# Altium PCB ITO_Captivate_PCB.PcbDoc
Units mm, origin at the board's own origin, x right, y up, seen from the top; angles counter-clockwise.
Board outline 77 x 64 mm, 2 copper layers (Top Layer, Bottom Layer), stack 1.575 mm thick; 24 components, 38 nets, 142 pads, 26 vias.
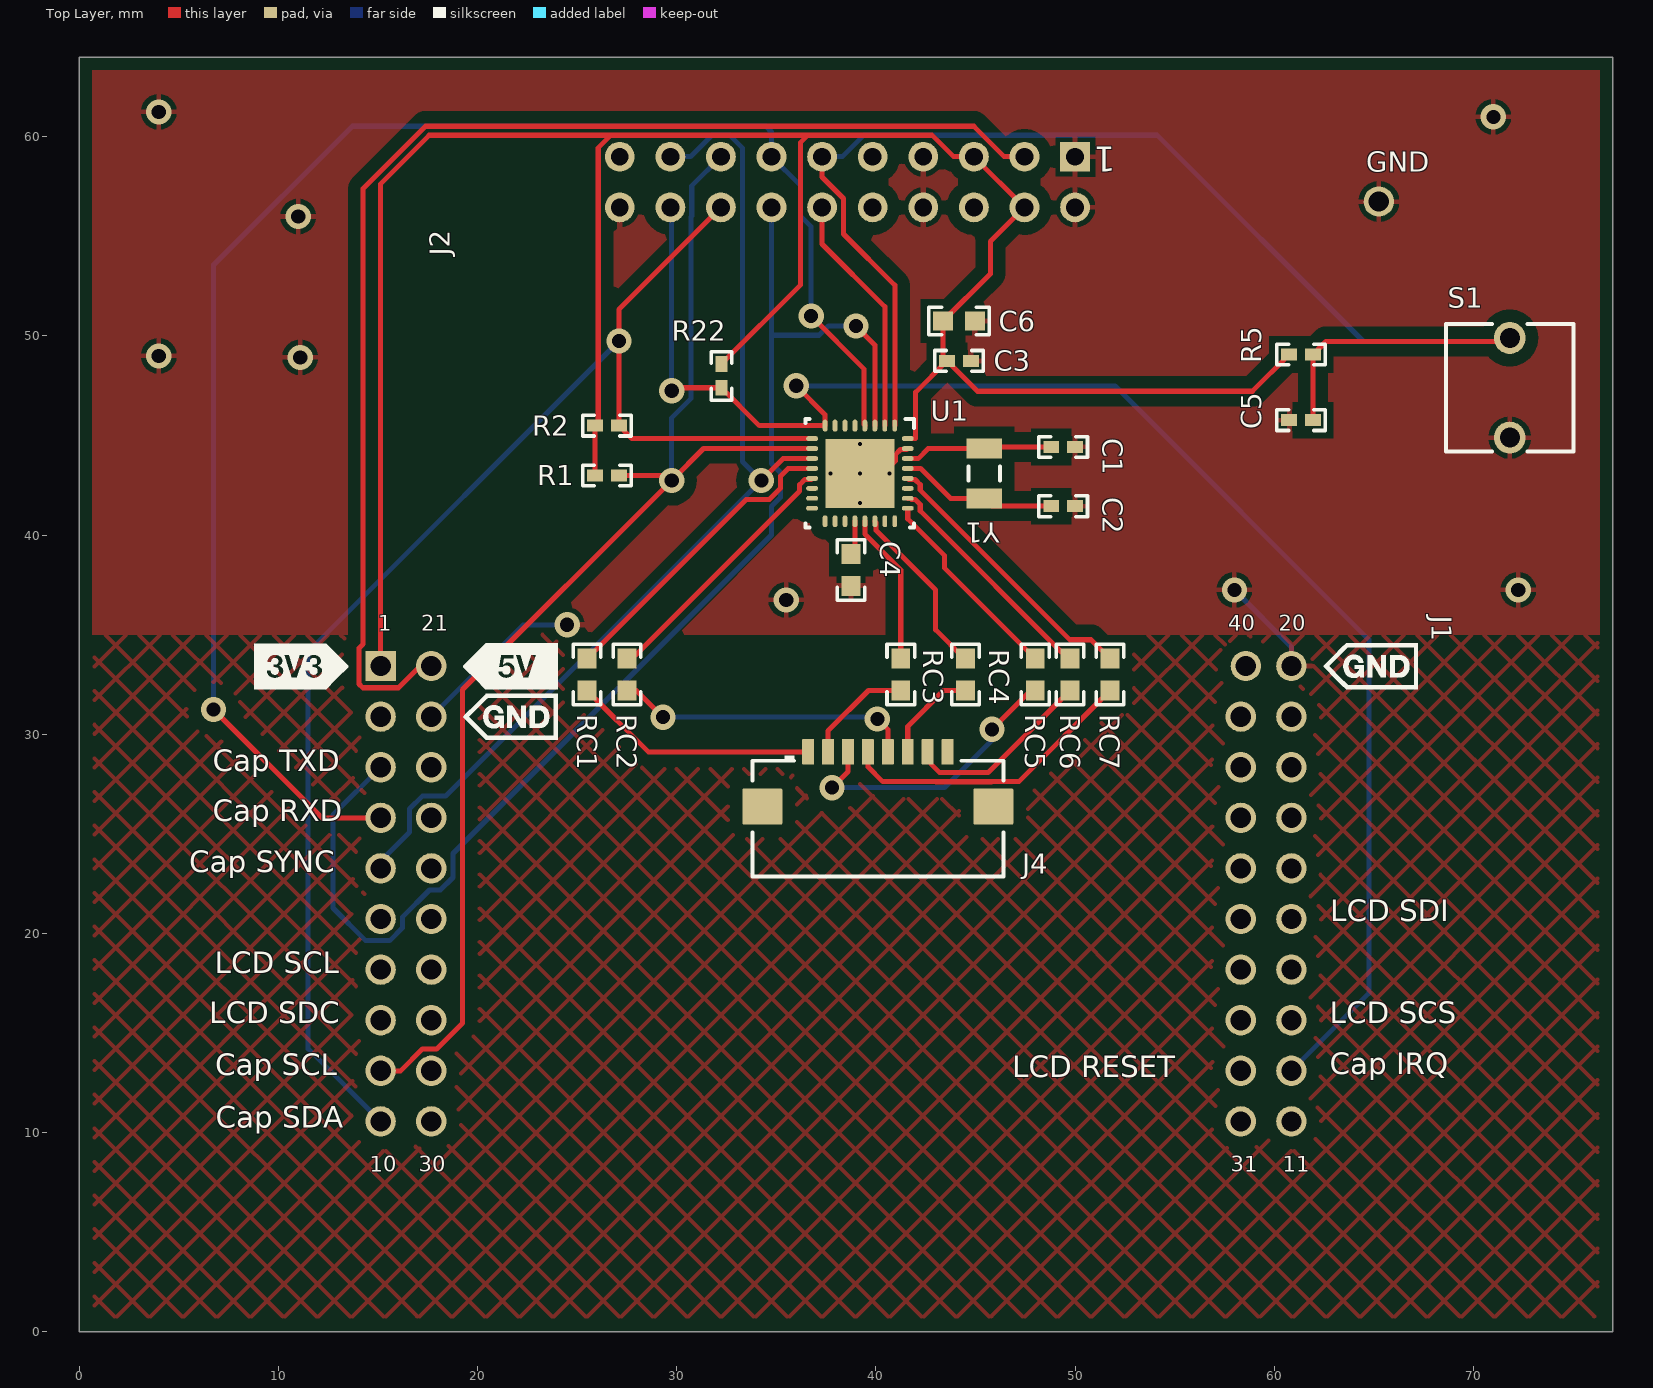
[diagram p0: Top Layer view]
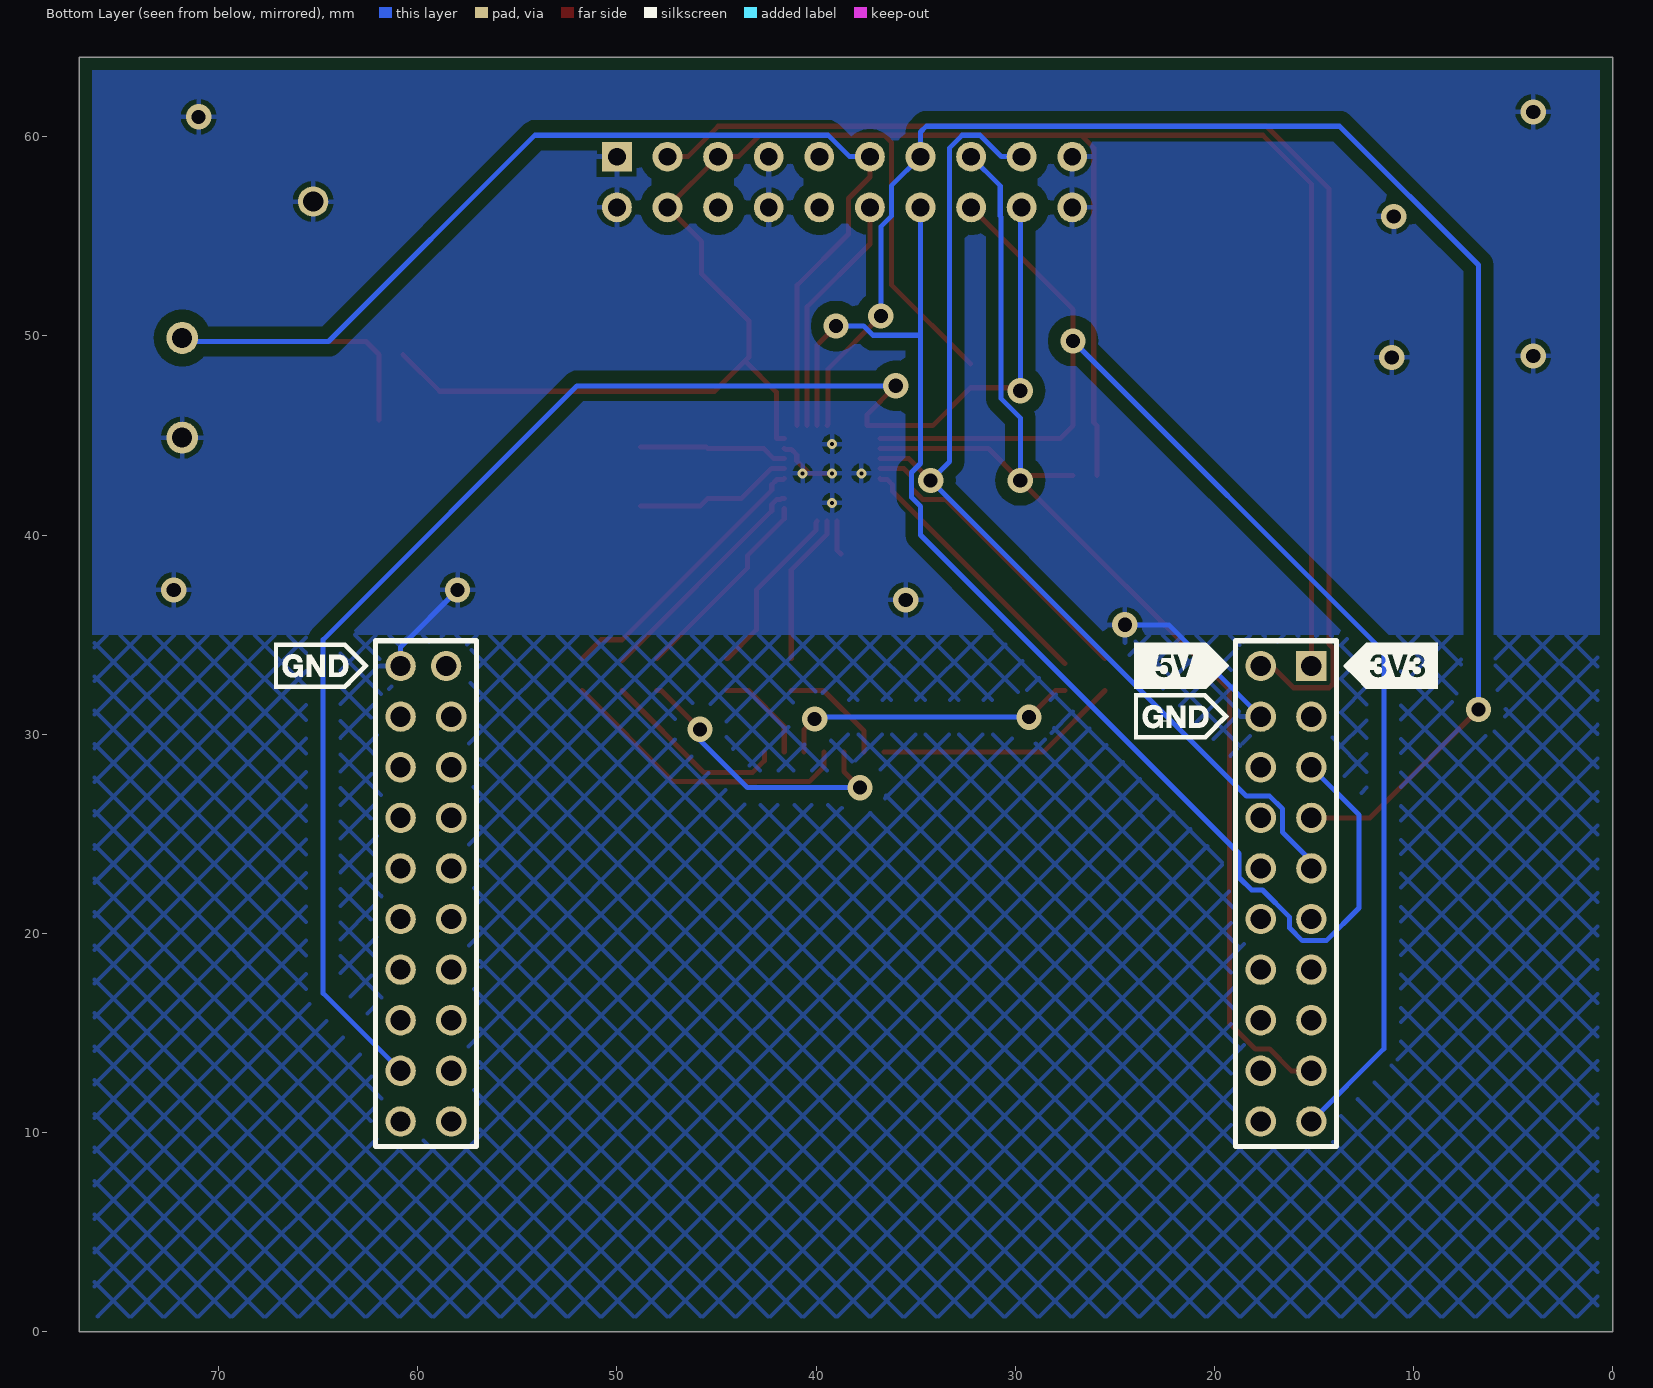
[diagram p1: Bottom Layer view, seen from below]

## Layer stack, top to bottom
Top Solder: solder mask 0.0102, Solder Resist, Dk 3.5
Top Layer: signal copper 0.0356
Dielectric1: core 1.5037, FR-4, Dk 4.8
Bottom Layer: signal copper 0.0356
Bottom Solder: solder mask 0.0102, Solder Resist, Dk 3.5

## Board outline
0,0 77,0 77,64 0,64

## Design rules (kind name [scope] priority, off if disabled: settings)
AcuteAngle [All] p1: minimum=4.50000000000000E+0001 checktracksonly=FALSE
AssemblyTestPointUsage [All] p1: valid=2
BoardOutlineClearance BoardOutlineClearance_MountingHoles [OnCopper and InComponentClass('Mounting Holes')] p1: gap=1.016
BoardOutlineClearance BoardOutlineClearance_Poly [OnCopper and IsPoly] p2: gap=0.635
BoardOutlineClearance [OnCopper and Not InComponentClass('Logo') and not InComponentClass('FiducialMark') and not InRegion(1000,500,4000,800) and not InPoly] p3: gap=1.905
Clearance Clearance_Keepouts [((IsTrack Or IsArc) And Not InPoly) And IsFree and IsKeepOut vs ((IsTrack Or IsArc) And Not InPoly) And IsFree and IsKeepOut] p1: gap=0
Clearance Clearance_Poly [InPolygon] p2: gap=0.635
Clearance [All] p3: gap=0.2
ComponentClearance ComponentClearance_MountingHoles_FiducialMarks [InComponentClass('Mounting Holes') vs InComponentClass('FiducialMark')] p1: gap=1.27 collisioncheckmode=3 verticalgap=0.254 showdistances=FALSE
ComponentClearance ComponentClearance_Shunt [InComponentClass('Header') vs InComponentClass('Shunt')] p2: gap=0 collisioncheckmode=3 verticalgap=0 showdistances=FALSE
ComponentClearance ComponentClearance_Logo [InComponentClass('Logo')] p3: gap=1.27 collisioncheckmode=3 verticalgap=0.254 showdistances=FALSE
ComponentClearance ComponentClearance_ScrewToNut [(HasFootprint('NY PMS 440 0025 PH')) vs (HasFootprint('Keystone_1902C'))] p4: gap=0.127 collisioncheckmode=3 verticalgap=0.254 showdistances=FALSE
ComponentClearance ComponentClearance_MountingHoles [InComponentClass('Mounting Holes')] p5: gap=6.35 collisioncheckmode=3 verticalgap=2540 showdistances=FALSE
ComponentClearance ComponentClearance_SmallPassives [HasFootprint('0201*') or HasFootprint('0402*') or HasFootprint('0508') or HasFootprint('0603*') or HasFootprint('0612') or HasFootprint('0805*') or HasFootprint('0815*') or HasFootprint('0830*') or HasFootprint('1206*') or HasFootprint('1210*') or HasFootprint('1808*') or HasFootprint('1812*') or HasFootprint('1825*') or HasFootprint('2010*') or HasFootprint('2220*') or HasFootprint('2225*') or HasFootprint('2512*') or HasFootprint('2728*') or HasFootprint('3518*') vs HasFootprint('0201*') or HasFootprint('0402*') or HasFootprint('0508') or HasFootprint('0603*') or HasFootprint('0612') or HasFootprint('0805*') or HasFootprint('0815*') or HasFootprint('0830*') or HasFootprint('1206*') or HasFootprint('1210*') or HasFootprint('1808*') or HasFootprint('1812*') or HasFootprint('1825*') or HasFootprint('2010*') or HasFootprint('2220*') or HasFootprint('2225*') or HasFootprint('2512*') or HasFootprint('2728*') or HasFootprint('3518*')] p6: gap=0.38 collisioncheckmode=3 verticalgap=0.254 showdistances=FALSE
ComponentClearance ComponentClearance_THtoSMT [IsThruComponent vs IsSMTComponent] p7: gap=1.016 collisioncheckmode=3 verticalgap=0.762 showdistances=FALSE
ComponentClearance ComponentClearance_THtoTH [IsThruComponent vs IsThruComponent] p8: gap=0.762 collisioncheckmode=3 verticalgap=0.762 showdistances=FALSE
ComponentClearance [All] p9: gap=0.762 collisioncheckmode=3 verticalgap=0.254 showdistances=FALSE
DiffPairsRouting [All] p1: maxlimit=2.54 minlimit=0.254 mostfreqgap=0.254 toplayer_minwidth=0.381 toplayer_maxwidth=0.381 toplayer_prefwidth=0.381 bottomlayer_minwidth=0.381 bottomlayer_maxwidth=0.381 bottomlayer_prefwidth=0.381 maxuncoupledlength=25.4
FabricationTestPointUsage TestPointUsage [All] p1: valid=2 allowmultiple=FALSE
FabricationTestpoint Testpoint [All] p1: side=3 testpointundercomponent=TRUE minsize=1.016 maxsize=2.54 preferedsize=1.524 minholesize=0 maxholesize=1.016 preferedholesize=0.813 testpointgrid=0.025 allowsidetop=TRUE allowsidebottom=TRUE usegrid=TRUE gridtolerance=0
FanoutControl Fanout_LCC [IsLCC] p1: bgadir=Out bgaviamode=Centered fanoutstyle=Auto fanoutdirection=Alternating viagrid=0.025 // Fanout_LCC (Default Rule)
FanoutControl Fanout_BGA [IsBGA] p2: bgadir=Out bgaviamode=Centered fanoutstyle=Auto fanoutdirection=Alternating viagrid=0.025 // Fanout_BGA (Default Rule)
FanoutControl Fanout_Default [All] p4: bgadir=Out bgaviamode=Centered fanoutstyle=Auto fanoutdirection=Alternating viagrid=0.025 // Fanout_Default (Default Rule)
FanoutControl Fanout_Small [(CompPinCount < 5)] p5: bgadir=Out bgaviamode=Centered fanoutstyle=Auto fanoutdirection=OutThenIn viagrid=0.025 // Fanout_Small (Default Rule)
HoleSize [All] p1: absolutevalues=TRUE maxlimit=6.375 minlimit=0.2 maxpercent=80.000 minpercent=20.000
MinimumAnnularRing MinimumAnnularRing_ThermalPadVias [IsVia and InAnyComponent] p1: minimumring=0.15
MinimumAnnularRing [All] p2: minimumring=0.203
MinimumSolderMaskSliver MinimumSolderMaskSliver_Logo [InComponentClass('Logo') vs InComponentClass('Logo')] p1: minsoldermaskwidth=0.018
MinimumSolderMaskSliver [All] p2: minsoldermaskwidth=0.1
PlaneConnect [All] p1: planeconnectstyle=Relief reliefexpansion=0.254 reliefentries=4 reliefconductorwidth=0.254 reliefairgap=0.254
PolygonConnect [All] p1: connectstyle=Relief reliefconductorwidth=0.254 reliefentries=4 polygonreliefangle="90 Angle" airgapwidth=0.254
RoutingVias ThermalPadVias [IsVia and InAnyComponent] p1: holewidth=0.2 width=0.5 viastyle="Through Hole" minholewidth=0.2 minwidth=0.5 maxholewidth=0.33 maxwidth=0.6
RoutingVias [All] p2: holewidth=0.406 width=0.864 viastyle="Through Hole" minholewidth=0.2 minwidth=0.66 maxholewidth=1.016 maxwidth=1.651
SilkToBoardRegionClearance [Not ((IsComment or IsDesignator) And (Hide <> 'False')) and not InRegion(1000,500,4000,800)] p1:
SilkToSilkClearance SilkToSilkClearance_Pb-FreeLogo [(HasFootprint('Pb-Free_Overlay_Medium') OR HasFootprint('Pb-Free_Overlay_Small')) vs (HasFootprint('Pb-Free_Overlay_Medium') OR HasFootprint('Pb-Free_Overlay_Small'))] p1: silktosilkclearance=0
SilkToSilkClearance [All] p2: silktosilkclearance=0.102
SilkToSolderMaskClearance SilkToComponentPadClearance [IsPad and InAnycomponent] p1: minsilkscreentomaskgap=0.127 clearancetoexposedcopper=TRUE
SilkToSolderMaskClearance "Silk to Solder Mask Opening" [All] p2: minsilkscreentomaskgap=0.102 clearancetoexposedcopper=FALSE
SolderMaskExpansion [All] p1: expansion=0.05
Width [All] p1: maxlimit=2.54 minlimit=0.152 preferedwidth=0.254 checkconnectedcopper=TRUE
15 further rules are at their usual default settings.

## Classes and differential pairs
component class Header: J1

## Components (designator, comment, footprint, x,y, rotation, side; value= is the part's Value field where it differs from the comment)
C1 "GRM1555C1H220JA01D" 0402 49.406,44.431 r0 top
C2 "GRM1555C1H220JA01D" 0402 49.406,41.456 r0 top
C3 "885012205037" 0402 44.175,48.75 r0 top
C4 "GRM188R61A105KA61D" 0603 38.75,38.25 r270 top
C5 "GRM155R61H102KA01D" 0402 61.35,45.775 r180 top
C6 "GRM185C81A475ME11D" 0603 44.175,50.75 r0 top
GND "TESTPOINT" TP_VIA_060RND040 65.25,56.75 r0 top
J1 "TSW-110-07-G-S" "40Pin BP" 38,22 r0 top
J2 "Connector 10X2RA" CONN2X10RA 50,59 r180 top
J4 "686108148922" Wurth_686108148922 40.1,27.75 r0 top
R1 "CRCW04022K20JNED" 0402 26.5,43 r180 top
R2 "CRCW04022K20JNED" 0402 26.5,45.5 r180 top
R5 "CRCW040247K0JNED" 0402 61.35,49.075 r180 top
R22 "CRCW040210K0JNED" 0402 32.25,48 r90 top
RC1 "ERJ-3GEY0R00V" 0603 25.5,33 r270 top
RC2 "ERJ-3GEY0R00V" 0603 27.5,33 r270 top
RC3 "ERJ-3GEY0R00V" 0603 41.25,33 r270 top
RC4 "ERJ-3GEY0R00V" 0603 44.5,33 r270 top
RC5 "ERJ-3GEY0R00V" 0603 48,33 r270 top
RC6 "ERJ-3GEY0R00V" 0603 49.75,33 r270 top
RC7 "ERJ-3GEY0R00V" 0603 51.75,33 r270 top
S1 "EVQ-21505R" SW_EVQ-21x05 71.825,47.4 r90 top
U1 "MSP430FR2633IRHB" RHB0032E 39.2,43.1 r270 top
Y1 "FC-135 32.7680KA-A3" Epson_FC-135 45.443,43.091 r270 top

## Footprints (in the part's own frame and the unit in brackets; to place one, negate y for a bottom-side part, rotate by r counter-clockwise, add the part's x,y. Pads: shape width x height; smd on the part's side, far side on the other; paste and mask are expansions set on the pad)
"40Pin BP" [mil] "40Pin Booster Pack Connection (Top - male; Bottom - female)"
  rect 60x60 hole 40: 1(-900,450)
  round 60 hole 40: 2(-900,350) 3(-900,250) 4(-900,150) 5(-900,50) 6(-900,-50) 7(-900,-150) 8(-900,-250) 9(-900,-350) 10(-900,-450) 11(900,-450) 12(900,-350) 13(900,-250) 14(900,-150) 15(900,-50) 16(900,50) 17(900,150) 18(900,250) 19(900,350) 20(900,450) 21(-800,450) 22(-800,350) 23(-800,250) 24(-800,150) 25(-800,50) 26(-800,-50) 27(-800,-150) 28(-800,-250) 29(-800,-350) 30(-800,-450) 31(800,-450) 32(800,-350) 33(800,-250) 34(800,-150) 35(800,-50) 36(800,50) 37(800,150) 38(800,250) 39(800,350) 40(810,450)
  silkscreen extent -1150,305 1150,495, body extent -950,-500 950,500, height 335
0402 [mm] "0402 from SM-752 data"
  rect 0.8x0.6 smd: 1(-0.6,0) 2(0.6,0)
  silkscreen extent -1.22,-0.52 1.22,0.52, body extent -0.55,-0.3 0.55,0.3, height 0.6
0603 [mm] "0603 from SM-752 data"
  rect 1x0.95 smd: 1(-0.8,0) 2(0.8,0)
  silkscreen extent -1.52,-0.69 1.52,0.69, body extent -0.87,-0.47 0.87,0.47, height 1
CONN2X10RA [mm] "Connector;F-Receptacle; 10x2 Position; Right Angle"
  rect 1.5x1.5 hole 0.9: 1(0,0)
  round 1.5 hole 0.9: 2(0,2.54) 3(2.54,0) 4(2.54,2.54) 5(5.08,0) 6(5.08,2.54) 7(7.62,0) 8(7.62,2.54) 9(10.16,0) 10(10.16,2.54) 11(12.7,0) 12(12.7,2.54) 13(15.24,0) 14(15.24,2.54) 15(17.78,0) 16(17.78,2.54) 17(20.32,0) 18(20.32,2.54) 19(22.86,0) 20(22.86,2.54)
  body extent -1.52,-10.03 24.38,-1.52, height 4.95
Epson_FC-135 [mm] "SMD, 2-Leads, Body 3.2x1.5mm"
  rect 1x1.8 smd: 1(-1.25,0) 2(1.25,0)
  silkscreen extent -0.35,-0.8 0.35,0.8, body extent -1.65,-0.8 1.65,0.8, height 0.9
RHB0032E [mm] "QFN, 32-Leads, Body 5x5mm, Pitch 0.5mm, Thermal Pad 3.45x3.45mm, TI Recommended"
  oval 0.6x0.24 smd: 1(-2.4,1.75) 2(-2.4,1.25) 3(-2.4,0.75) 4(-2.4,0.25) 5(-2.4,-0.25) 6(-2.4,-0.75) 7(-2.4,-1.25) 8(-2.4,-1.75) 17(2.4,-1.75) 18(2.4,-1.25) 19(2.4,-0.75) 20(2.4,-0.25) 21(2.4,0.25) 22(2.4,0.75) 23(2.4,1.25) 24(2.4,1.75)
  oval 0.24x0.6 smd: 9(-1.75,-2.4) 10(-1.25,-2.4) 11(-0.75,-2.4) 12(-0.25,-2.4) 13(0.25,-2.4) 14(0.75,-2.4) 15(1.25,-2.4) 16(1.75,-2.4) 25(1.75,2.4) 26(1.25,2.4) 27(0.75,2.4) 28(0.25,2.4) 29(-0.25,2.4) 30(-0.75,2.4) 31(-1.25,2.4) 32(-1.75,2.4)
  rect 3.45x3.45 smd paste-1.725: 33(0,0)
  silkscreen extent -2.72,-2.73 2.72,2.73, body extent -2.57,-2.57 2.58,2.58, height 1.01
SW_EVQ-21x05 [mm] "Panasonic"
  round 1.6 hole 1: 1(-2.5,0) 2(2.5,0)
  silkscreen extent -3.2,-3.2 3.2,3.2, body extent -3.15,-3.15 3.15,3.15, height 5.2
TP_VIA_060RND040 [mil] "TP_VIA_060RND040"
  round 60 hole 40: 1(0,0)
Wurth_686108148922 [mm] "FFC/FPC Connector, 8 POS, 1mm, R/A, SMT"
  rrect17% 0.6x1.3 smd: 1(-3.5,1.375) 2(-2.5,1.375) 3(-1.5,1.375) 4(-0.5,1.375) 5(0.5,1.375) 6(1.5,1.375) 7(2.5,1.375) 8(3.5,1.375)
  rrect6% 2x1.8 smd: MP1(-5.8,-1.375) MP2(5.8,-1.375)
  silkscreen extent -6.3,-4.87 6.3,1.2, body extent -6.3,-4.87 6.3,1.63, height 2.25

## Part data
C1 C2: "CAP, CERM, 22 pF, 50 V, +/- 5%, C0G/NP0, 0402"
C3: "CAP, CERM, 0.1 µF, 16 V, +/- 10%, X7R, 0402"
C4: "CAP, CERM, 1 µF, 10 V, +/- 10%, X5R, 0603"
C5: "CAP, CERM, 1000 pF, 50 V, +/- 10%, X5R, 0402"
C6: "CAP, CERM, 4.7 µF, 10 V, +/- 20%, X6S, 0603"
GND: "TEST POINT.  No entry in BOM."
J1: library part "BoosterPack Connector", "Header, 100mil, 10x1, Gold, TH"
J2: "Connector, Female, 10-Pin, 2 row, Right Angle"
J4: "FFC/FPC Connector, 8 POS, 1mm, Tin, R/A, SMT"
R1 R2: "RES, 2.2 k, 5%, 0.063 W, 0402"
R5: "RES, 47k ohm, 5%, 0.063W, 0402"
R22: "RES, 10 k, 5%, 0.063 W, 0402"
RC1 RC2 RC3 RC4 RC5 RC6 RC7: "RES, 0, 5%, 0.1 W, 0603"
S1: "Switch, Tactile, SPST-NO, 0.02A, 15V, TH"
U1: "MSP430 Captivate Microcontroller"
Y1: "Crystal, 32.768 KHz, 12.5 pF, SMD"

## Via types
v1: diameter 1.27, hole 0.711, Top Layer to Bottom Layer, 21 vias
v2: diameter 0.5, hole 0.2, Top Layer to Bottom Layer, 5 vias

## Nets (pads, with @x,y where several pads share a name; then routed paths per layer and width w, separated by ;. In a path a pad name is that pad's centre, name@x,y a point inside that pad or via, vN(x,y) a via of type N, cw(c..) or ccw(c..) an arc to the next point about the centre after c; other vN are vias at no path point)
BUTTON1: J4.1 RC1.2 | length 12.4
  Top Layer w0.254: RC1.2 28.575,29.125 J4.1
BUTTON2: J4.2 RC3.2 | length 5.5
  Top Layer w0.254: J4.2 37.6,30.175 39.625,32.2 RC3.2
BUTTON3: J4.3 RC5.2 | length 14.7
  Top Layer w0.254: v1(37.8,27.325) 38.6,28.125 J4.3 ; v1(45.825,30.25) 47.775,32.2 RC5.2
  Bottom Layer w0.254: v1(37.8,27.325) 43.45,27.325 45.825,29.7 v1(45.825,30.25)
EZFET_RXD: J2.9
EZFET_SBWTCK_TST: J2.12 U1.2 | length 12.3
  Top Layer w0.254: J2.12 37.3,54.62 40.45,51.47 U1.2
EZFET_SBWTDIO_RST: C5.1 J2.11 R5.1 S1.2 U1.1 | length 67.9
  Top Layer w0.254: J2.11 37.3,57.983 38.377,56.906 38.377,55.123 40.95,52.55 U1.1 ; C5.1 R5.1 62.6,49.725 71.65,49.725 S1.2
  Bottom Layer w0.254: J2.11 38.317,59 39.394,60.077 54.123,60.077 64.475,49.725 71.65,49.725 S1.2
EZFET_TXD: J2.10
GND: C1.2 C2.2 C3.2 C4.2 C5.2 C6.2 GND.1 J1.20 J1.22 J2.1 J2.2 J2.7 J2.8 J2.19 J2.20 S1.1 U1.31 U1.33 | length 16.8
  Top Layer w0.254: v2(39.2,43.1) 40.35,43.1 40.973,43.723 40.973,44.035 41.235,44.297 41.547,44.297 U1.31
  Bottom Layer w0.254: J1.22 22.29,35.5 v1(24.5,35.5) ; v1(58,37.25) 60.86,34.39 J1.20
  other v1: 35.5,36.75 72.25,37.25 11.1,48.925 4,49 11,56 71,61 4,61.25
  other v2: 39.2,41.625 37.725,43.1 40.675,43.1 39.2,44.575
LCD_SCL: J1.7
LCD_SCS: J1.13
LCD_SDC: J1.8
LCD_SDI: J1.15
MSP_IRQ: J1.12 J2.18 R22.1 U1.8 | length 77.9
  Top Layer w0.254: v1(29.75,47.25) 29.9,47.4 R22.1 34.15,45.5 U1.8 37.45,46.05 v1(36,47.5)
  Bottom Layer w0.254: J2.18 29.75,56.39 v1(29.75,47.25) ; v1(36,47.5) 36.25,47.75 36.5,47.5 52,47.5 64.75,34.75 64.75,17 J1.12
MSP_RXD: J1.4 J2.13 U1.4 | length 80.7
  Top Layer w0.254: v1(6.75,31.25) 12.19,25.81 J1.4 ; v1(36.75,51) 39.397,48.353 39.397,45.553 U1.4
  Bottom Layer w0.254: v1(6.75,31.25) 6.75,53.562 13.719,60.531 34.469,60.531 34.76,60.24 J2.13 36.223,57.537 36.223,56.014 36.75,55.487 v1(36.75,51)
MSP_SCL: J1.9 J2.15 R1.1 U1.10 | length 64.7
  Top Layer w0.254: J1.9@15.14,12.89 J1.9 16.14,13.11 17.229,14.199 17.949,14.199 19.25,15.5 19.25,32.25 v1(29.75,42.75) ; R1.1 29.5,43 v1(29.75,42.75) ; U1.10 31.35,44.35 v1(29.75,42.75)
  Bottom Layer w0.254: v1(29.75,42.75) 29.75,45.89 30.712,46.852 30.712,55.969 30.757,56.014 30.757,57.537 J2.15
MSP_SDA: J1.10 J2.16 R2.1 U1.9 | length 70.2
  Top Layer w0.254: J2.16 27.1,51.34 v1(27.1,49.75) R2.1 27.75,44.85 U1.9
  Bottom Layer w0.254: J1.10 11.5,14.21 11.5,34.15 v1(27.1,49.75)
MSP_SYNC: J1.5 J2.17 U1.11 | length 52.5
  Top Layer w0.254: v1(34.25,42.75) 35.35,43.85 U1.11
  Bottom Layer w0.254: J1.5 15.14,23.64 16.591,25.091 16.591,26.261 17.229,26.899 18.399,26.899 v1(34.25,42.75) 33.297,43.703 33.297,59.446 32.666,60.077 31.774,60.077 30.697,59 J2.17
MSP_TXD: J1.3 J2.14 U1.3 | length 66.9
  Top Layer w0.254: v1(39,50.5) 39.95,49.55 U1.3
  Bottom Layer w0.254: J1.3 12.75,25.96 12.75,21.282 14.391,19.641 15.591,19.641 16.229,20.279 16.229,20.819 17.591,22.181 18.131,22.181 18.769,22.819 18.769,24.019 34.76,40.01 34.76,41.448 35.212,41.9 35.212,43.148 34.76,43.6 34.76,50.05 ; J2.14 34.76,50.05 ; v1(39,50.5) 37.61,50.5 37.148,50.038 34.772,50.038 34.76,50.05
NetRC1_1: RC1.1 U1.12 | length 15.6
  Top Layer w0.254: RC1.1 33.488,41.788 34.648,41.788 35.212,42.352 35.212,42.962 35.6,43.35 U1.12
NetRC2_1: RC2.1 U1.13 | length 13.3
  Top Layer w0.254: RC2.1@27.5,33.55 36.173,42.223 36.173,42.535 36.435,42.797 36.747,42.797 U1.13
NetRC3_1: RC3.1 U1.21 | length 7.6
  Top Layer w0.254: U1.21 39.45,40.05 41.25,38.25 RC3.1
NetRC4_1: RC4.1 U1.22 | length 8.8
  Top Layer w0.254: U1.22 40.003,40.647 40.003,40.247 43,37.25 43,35.25 44.45,33.8 RC4.1
NetRC5_1: RC5.1 U1.25 | length 10.2
  Top Layer w0.254: U1.25 41.6,40.821 43.454,38.967 43.454,38.346 RC5.1
NetRC6_1: RC6.1 U1.26 | length 11.7
  Top Layer w0.254: U1.26 41.742,41.85 41.795,41.797 41.965,41.797 42.227,41.535 42.227,41.223 RC6.1@49.75,33.7
NetRC7_1: RC7.1 U1.28 | length 14.1
  Top Layer w0.254: U1.28 41.653,42.797 41.965,42.797 42.227,42.535 42.227,42.261 49.738,34.75 50.8,34.75 RC7.1
P1.0: U1.7
P1.6/LED2: U1.5
P1.7/LED1: U1.6
PROXIMITY: J4.4 RC7.2 | length 15.1
  Top Layer w0.254: J4.4 39.6,28.375 40.35,27.625 43.008,27.625 43.012,27.621 45.813,27.621 45.817,27.625 47.175,27.625 RC7.2
SLIDER1: J4.5 RC2.2 | length 15
  Top Layer w0.254: RC2.2 27.976,32.2 v1(29.311,30.866) ; v1(40.075,30.775) 40.6,30.25 J4.5
  Bottom Layer w0.254: v1(29.311,30.866) 39.984,30.866 v1(40.075,30.775)
SLIDER2: J4.6 RC4.2 | length 4.9
  Top Layer w0.254: J4.6 41.6,30.4 43.4,32.2 RC4.2
SLIDER3: J4.7 RC6.2 | length 9.6
  Top Layer w0.254: J4.7 42.6,28.675 43.2,28.075 45.625,28.075 RC6.2
VCC_5V: J1.21 J2.3 | length 64.2
  Top Layer w0.254: J1.21 17.126,33.43 16.037,32.341 14.243,32.341 14.051,32.533 14.051,34.327 14.25,34.526 14.25,57.392 17.389,60.531 44.912,60.531 46.443,59 J2.3
VCC_LDO: C3.1 C6.1 J1.1 J2.4 J2.5 R1.2 R2.2 R5.2 R22.2 U1.32 | length 122.7
  Top Layer w0.254: J1.1 15.14,57.64 17.577,60.077 26.694,60.077 ; R1.2 R2.2 26.063,45.663 26.063,59.446 26.694,60.077 ; R22.2 36.223,52.573 36.223,59.723 36.5,60 36.5,60.077 ; U1.32 42,44.85 42,47.175 C3.1 ; R5.2 58.9,47.225 45.1,47.225 C3.1 ; 26.694,60.077 36.5,60.077 ; 36.5,60.077 42.826,60.077 43.903,59 J2.5 J2.4 45.75,54.75 45.75,53.125 C6.1 43.375,48.95 C3.1
VCC_METERED: J2.6
VREG: C4.1 U1.20 | length 1.7
  Top Layer w0.254: C4.1 38.95,39.25 U1.20
XIN: C1.1 U1.30 Y1.1 | length 7.4
  Top Layer w0.254: U1.30@41.6,43.843 42.122,43.843 42.621,44.341 Y1.1 45.533,44.431 C1.1
XOUT: C2.1 U1.29 Y1.2 | length 8
  Top Layer w0.254: U1.29 42.25,43.35 43.759,41.841 Y1.2 45.828,41.456 C2.1
pads on no net: J1.2 J1.6 J1.11 J1.14 J1.16 J1.17 J1.18 J1.19 J1.23 J1.24 J1.25 J1.26 J1.27 J1.28 J1.29 J1.30 J1.31 J1.32 J1.33 J1.34 J1.35 J1.36 J1.37 J1.38 J1.39 J1.40 J4.8 J4.MP1 J4.MP2 U1.14 U1.15 U1.16 U1.17 U1.18 U1.19 U1.23 U1.24 U1.27

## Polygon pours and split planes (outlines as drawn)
GND on Top Layer "TOP_LAYER_GND_P008" (hatched 45Degree grid 1.194 track 0.203, remove dead copper, pour order 8): 77,35 0,35 0,0 77,0 77,35
GND on Top Layer "TOP_LAYER_GND_P000" (solid, remove dead copper, pour order 0): 0,35 77,35 77,64 0,64 0,35
GND on Bottom Layer "BOTTOM_LAYER_GND_P012" (hatched 45Degree grid 1.194 track 0.203, remove dead copper, pour order 12): 77,35 0,35 0,0 77,0 77,35
GND on Bottom Layer "BOTTOM_LAYER_GND_P002" (solid, remove dead copper, pour order 2): 0,35 77,35 77,64 0,64 0,35

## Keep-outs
Keep-Out Layer:
  text ".Layer_Name" at 14.656,-21.806 h1.52

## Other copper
Top Layer:
  text ".Layer_Name" at 14.656,-21.806 h1.52
Bottom Layer:
  text ".Layer_Name" at 14.656,-21.806 h1.52

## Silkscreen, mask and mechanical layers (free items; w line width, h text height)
Top Overlay:
  text "Cap TXD" at 6.7,27.775 h1.85
  text "Cap RXD" at 6.7,25.25 h1.85
  text "Cap SYNC" at 5.525,22.7 h1.85
  text "LCD SDI" at 62.8,20.25 h1.85
  text "LCD SCL" at 6.8,17.625 h1.85
  text "LCD SDC" at 6.525,15.125 h1.85
  text "LCD SCS" at 62.775,15.125 h1.85
  text "Cap IRQ" at 62.775,12.55 h1.85
  text "Cap SCL" at 6.825,12.5 h1.85
  text "LCD RESET" at 46.85,12.4 h1.85
  text "Cap SDA" at 6.85,9.875 h1.85
  text ".Layer_Name" at 14.656,-21.806 h1.52
Bottom Overlay:
  text ".Layer_Name" at 14.656,-21.806 h1.52
Top Paste:
  text ".Layer_Name" at 14.656,-21.806 h1.52
Bottom Paste:
  text ".Layer_Name" at 14.656,-21.806 h1.52
Top Solder:
  text ".Layer_Name" at 14.656,-21.806 h1.52
  text ".Layer_Name" at 14.656,-21.806 h1.52
Bottom Solder:
  text ".Layer_Name" at 14.656,-21.806 h1.52
Drill Guide:
  text ".Layer_Name" at 14.656,-21.806 h1.52
M1 Board Outline:
  the board outline again, w0.254
  text ".Layer_Name" at 14.656,-21.806 h1.52
M2 Board Dimensions:
  rectangle: 3.175,-10.16 12.7,-6.985
  rectangle: 0,-6.985 3.175,-3.81
  lines w0.178: 0,-6.985 25.4,-6.985 ; 0,-3.81 0,-10.16 25.4,-10.16 25.4,-3.81 ; 3.175,-10.16 3.175,-3.81 ; 6.35,-10.16 6.35,-3.81 ; 12.7,-10.16 12.7,-3.81 ; 19.05,-10.16 19.05,-3.81
  text ".Layer_Name" at 14.656,-21.806 h1.52
M3 3D STEP Top:
  text ".Layer_Name" at 14.656,-21.806 h1.52
M4 3D STEP Bottom:
  text ".Layer_Name" at 14.656,-21.806 h1.52
M5 Assembly Top:
  lines w0.254: -7.417,-23.626 160.223,-23.626 ; -7.417,-18.462 160.274,-18.462 ; -7.417,-13.297 -7.417,-28.791 94.31,-28.791 160.274,-28.791 160.274,-13.297 -7.404,-13.297 -7.404,-28.791 32.614,-28.791 ; 55.194,-28.791 55.194,-13.297 ; 87.376,-18.462 87.376,-13.297 ; 108.712,-18.462 108.712,-13.297 ; 124.511,-28.956 124.511,-23.804
  text "COMPONENTS MARKED 'DNP' SHOULD NOT BE POPULATED." at 29.299,-8.09 h1.52
  text "ASSEMBLY VARIANT:" at 29.286,-11.024 h1.52
  text ".VariantName" at 55.601,-11.024 h1.52
  text "PCB VIEWED FROM TOP SIDE" at -5.804,-16.654 h1.52
  text "BOARD #:" at 57.099,-16.654 h1.52
  text ".PRJ_Number" at 70.955,-16.654 h1.52
  text "REV:" at 92.405,-16.654 h1.52
  text ".PCB_Rev" at 99.809,-16.654 h1.52
  text "SVN REV:" at 113.69,-16.654 h1.52
  text ".VersionControl_RevNumber" at 126.543,-16.654 h1.52
  text "TID #:" at 57.099,-21.819 h1.52
  text ".TID" at 70.955,-21.819 h1.52
  text "PLOT NAME =" at -5.804,-27.034 h1.52
  text ".plot_File_Name" at 14.656,-27.034 h1.52
  text "GENERATED    :" at 57.15,-27.034 h1.52
  text ".Print_Date" at 79.235,-27.034 h1.52
  text ".Print_Time" at 97.752,-27.034 h1.52
  text "TEXAS INSTRUMENTS" at 129.87,-27.034 h1.52
M6 Assembly Bottom:
  lines w0.254: -7.429,-18.474 160.261,-18.474 ; -7.379,-23.639 160.261,-23.639 ; 28.334,-28.969 28.334,-23.817 ; 44.133,-18.474 44.133,-13.31 ; 65.468,-18.474 65.468,-13.31 ; 97.65,-28.804 97.65,-13.31 ; 120.231,-28.804 160.249,-28.804 160.249,-13.31 -7.429,-13.31 -7.429,-28.804 58.534,-28.804 160.261,-28.804 160.261,-13.31
  text "COMPONENTS MARKED 'DNP' SHOULD NOT BE POPULATED." at 154.991,-8.077 h1.52
  text ".VariantName" at 128.473,-11.024 h1.52
  text "ASSEMBLY VARIANT:" at 154.864,-11.024 h1.52
  text ".VersionControl_RevNumber" at 26.302,-16.667 h1.52
  text "SVN REV:" at 39.154,-16.667 h1.52
  text ".PCB_Rev" at 53.035,-16.667 h1.52
  text "REV:" at 60.439,-16.667 h1.52
  text ".PRJ_Number" at 81.89,-16.667 h1.52
  text "BOARD #:" at 95.745,-16.667 h1.52
  text "PCB VIEWED FROM BOTTOM SIDE" at 158.648,-16.667 h1.52
  text ".TID" at 81.89,-21.831 h1.52
  text "TID #:" at 95.745,-21.831 h1.52
  text "TEXAS INSTRUMENTS" at 22.974,-27.047 h1.52
  text ".Print_Time" at 55.093,-27.047 h1.52
  text ".Print_Date" at 73.609,-27.047 h1.52
  text "GENERATED    :" at 95.694,-27.047 h1.52
  text ".plot_File_Name" at 138.189,-27.047 h1.52
  text "PLOT NAME =" at 158.648,-27.047 h1.52
M9 Title Sheet:
  drawing of 57 lines, arcs and shapes, not listed
  text "1" at 18.792,204.127 h1.78
  text "2" at 82.182,204.127 h1.78
  text "3" at 145.411,204.127 h1.78
  text "4" at 209.08,204.127 h1.78
  text "5" at 272.555,204.127 h1.78
  text "6" at 336.182,204.127 h1.78
  text "A" at -10.579,175.095 h1.78
  text "A" at 365.341,175.095 h1.78
  text "B" at -10.579,114.643 h1.78
  text "B" at 365.341,114.643 h1.78
  text "C" at -10.579,54.318 h1.78
  text "C" at 365.341,54.318 h1.78
  text "PROJECT TITLE:" at 288.125,7.048 h1.14
  text ".PRJ_Title" at 289.395,3.662 h1.78
  text "DESIGNED FOR:" at 288.125,-0.597 h1.14
  text ".PRJ_Customer" at 289.395,-4.153 h1.78
  text "D" at -10.579,-5.88 h1.78
  text "D" at 365.341,-5.88 h1.78
  text "FILE NAME:" at 288.125,-8.217 h1.14
  text ".PCB_File_Name_No_Path" at 289.395,-11.265 h1.78
  text "Texas Instruments (TI) and/or its licensors do not warrant the accuracy or completeness of this specification" at 161.9,-15.376 h1.14
  text "ENGINEER:" at 288.125,-15.583 h1.14
  text "LAYOUT BY:" at 326.352,-15.583 h1.14
  text "or any information contained therein. TI and/or its licensors do not warrant that this design will meet" at 160.757,-18.237 h1.14
  text ".PRJ_Engineer" at 289.395,-19.52 h1.78
  text ".PCB_Layout" at 327.635,-19.52 h1.78
  text "the specifications, will be suitable for your application or fit for any particular purpose, or will operate in" at 160.757,-21.099 h1.14
  text ".Layer_Name" at 14.656,-21.806 h1.52
  text "ALTIUM DESIGNER VERSION:" at 326.352,-23.457 h1.14
  text "an implementation. TI and/or its licensors do not warrant that the design is production worthy. You should" at 160.757,-23.961 h1.14
  text "completely validate and test your design implementation to confirm the system functionality for your application." at 161.9,-26.822 h1.14
  text ".print_Scale" at 289.395,-26.843 h1.78
  text ".Application_BuildNumber" at 327.635,-26.843 h1.78
  text "1" at 18.792,-32.093 h1.78
  text "2" at 82.182,-32.093 h1.78
  text "3" at 145.411,-32.093 h1.78
  text "4" at 209.08,-32.093 h1.78
  text "5" at 272.555,-32.093 h1.78
  text "6" at 336.182,-32.093 h1.78
M10 Fab Notes:
  drawing of 173 lines, arcs and shapes, not listed
  text "DESIGN INFORMATION" at 314.402,157.505 h1.52
  text "MIN. TRACK WIDTH:" at 298.03,152.933 h1.52
  text "8" at 325.874,152.933 h1.52
  text "MIL" at 329.805,152.933 h1.52
  text "MIN. CLEARANCE:" at 298.03,149.581 h1.52
  text "0.2" at 324.35,149.581 h1.52
  text "mm" at 329.805,149.581 h1.52
  text "MIN. VIA PAD SIZE:" at 298.03,146.228 h1.52
  text "24" at 325.113,146.228 h1.52
  text "MIL" at 329.805,146.228 h1.52
  text "0.05mm (2MIL)" at 315.683,142.628 h1.52
  text "MINIMUM ANNULAR RING" at 289.667,142.52 h1.52
  text "EXTERNAL" at 333.666,142.52 h1.52
  text "PER" at 294.747,139.522 h1.52
  text "IPC-D-275 CLASS 2 LEVEL C" at 300.335,139.522 h1.52
  text "MIL, HOLES" at 338.136,136.67 h1.52
  text "+/-" at 328.168,136.652 h1.52
  text "+/-" at 349.86,136.652 h1.52
  text "REGISTRATION TOLERANCES:" at 289.667,136.525 h1.52
  text "METAL" at 320.142,136.525 h1.52
  text "5" at 334.777,136.525 h1.52
  text "3" at 355.935,136.525 h1.52
  text "MIL" at 358.888,136.525 h1.52
  text "+/-" at 349.86,133.655 h1.52
  text "HOLE SIZE TOLERANCE (UNLESS OTHERWISE SPECIFIED):" at 289.667,133.528 h1.52
  text "3" at 355.935,133.528 h1.52
  text "MIL" at 358.888,133.528 h1.52
  text "MATERIAL:" at 287.768,128.208 h1.52
  text "FR-4 High Tg" at 312.824,124.643 h1.52
  text "FR-408" at 298.462,124.425 h1.52
  text "OTHER" at 336.257,124.425 h1.52
  text "X" at 308.889,124.333 h1.52
  text "62 MIL (1.6mm) +/-10%" at 306.592,120.292 h1.52
  text "THICKNESS:" at 289.667,120.184 h1.52
  text "X" at 303.337,120.184 h1.52
  text "OTHER" at 339.229,120.184 h1.52
  text "TOLERANCE:" at 289.667,116.17 h1.52
  text "X" at 310.986,116.17 h1.52
  text "ANSI IPC-6012 TYPE 3 CLASS 2" at 315.734,116.17 h1.52
  text "OTHER +/-" at 315.734,112.208 h1.52
  text "BOW & TWIST:" at 289.667,108.22 h1.52
  text "X" at 310.986,108.22 h1.52
  text "ANSI IPC-6012 TYPE 3 CLASS 2" at 315.734,108.22 h1.52
  text "OTHER +/-" at 315.734,104.194 h1.52
  text "DRILLING:" at 287.768,100.676 h1.52
  text "REFERENCE:" at 289.667,97.705 h1.52
  text "X" at 306.132,97.705 h1.52
  text "AS SHOWN" at 310.882,97.705 h1.52
  text "X" at 329.018,97.705 h1.52
  text "NC_DRILL FILES" at 332.498,97.705 h1.52
  text "PTH COPPER THICKNESS:" at 289.667,93.691 h1.52
  text "X" at 318.375,93.691 h1.52
  text "20-30 um" at 321.855,93.691 h1.52
  text "OTHER" at 340.067,93.691 h1.52
  text "BOARD FINISH:" at 287.768,89.653 h1.52
  text "SILKSCREEN:" at 291.711,86.656 h1.52
  text "X" at 315.81,86.656 h1.52
  text "TOP" at 319.01,86.656 h1.52
  text "X" at 328.764,86.656 h1.52
  text "BOTTOM" at 331.99,86.656 h1.52
  text "SILKSCREEN COLOR:" at 291.711,82.414 h1.52
  text "X" at 315.783,82.414 h1.52
  text "WHITE" at 319.01,82.414 h1.52
  text "OTHER" at 331.99,82.414 h1.52
  text "X" at 319.111,78.37 h1.52
  text "GREEN" at 322.338,78.37 h1.52
  text "OTHER" at 338.035,78.37 h1.52
  text "SOLDER RESIST COLOR:" at 291.711,78.096 h1.52
  text "X" at 319.111,74.052 h1.52
  text "MATTE" at 322.338,74.052 h1.52
  text "SEMI-GLOSS" at 338.023,74.036 h1.52
  text "IMMERSION GOLD (ENIG)" at 314.718,69.264 h1.52
  text "ENEPIG" at 348.691,69.18 h1.52
  text "SURFACE FINISH:" at 287.768,69.155 h1.52
  text "X" at 309.969,69.155 h1.52
  text "IMM. TIN/SILVER OR EQUIV" at 296.139,65.167 h1.52
  text "OTHER" at 332.498,65.167 h1.52
  text "ARRAY/PANEL:" at 287.768,60.621 h1.52
  text "CUT AND TRIM PER M1 BOARD OUTLINE" at 314.718,60.512 h1.52
  text "N.C. ROUTE" at 314.718,56.658 h1.52
  text "X" at 331.964,56.658 h1.52
  text "V. SCORE" at 336.714,56.658 h1.52
  text "CERTIFICATION:" at 287.768,53.178 h1.52
  text "MATERIALS AND WORKMANSHIP FOR ALL PCBS" at 306.183,53.178 h1.52
  text "TO MEET OR EXCEED THE REQUIREMENTS OF:" at 306.183,50.689 h1.52
  text "X" at 296.696,47.222 h1.52
  text "ANSI IPC-A-600F CLASS ->" at 300.227,47.222 h1.52
  text "X" at 341.859,47.222 h1.52
  text "2" at 344.88,47.222 h1.52
  text "1" at 336.879,47.184 h1.52
  text "3" at 353.872,47.184 h1.52
  text "X" at 317.373,43.171 h1.52
  text "RoHS" at 320.852,43.171 h1.52
  text "OTHER" at 337.22,43.171 h1.52
  text "PER ORDER" at 347.305,43.171 h1.52
  text "ALL BOARDS MUST MEET OR EXCEED UL94-V0 REQUIREMENTS." at 288.468,38.964 h1.52
  text "PCB MUST BEAR THE UL94V-0 UL REGISTERED MATERIAL ID NUMBER" at 288.468,35.916 h1.52
  text "ADDITIONAL REQUIREMENTS:" at 287.768,31.512 h1.52
  text "MICROSECTION:" at 289.667,28.591 h1.52
  text "YES" at 312.673,28.591 h1.52
  text "REQUIRED" at 334.555,24.625 h1.52
  text "BARE BOARD ELEC. TEST:" at 289.667,24.553 h1.52
  text "NONE" at 322.833,24.553 h1.52
  text "X" at 331.329,24.553 h1.52
  text "PER ORDER" at 349.592,24.553 h1.52
  text ".Layer_Name" at 14.656,-21.806 h1.52
M11 Gerber Information:
  lines w0.254: -7.417,-23.626 160.223,-23.626 ; -7.417,-18.462 160.274,-18.462 ; -7.417,-13.297 -7.417,-28.791 94.31,-28.791 160.274,-28.791 160.274,-13.297 -7.404,-13.297 -7.404,-28.791 32.614,-28.791 ; 55.194,-28.791 55.194,-13.297 ; 87.376,-18.462 87.376,-13.297 ; 108.712,-18.462 108.712,-13.297 ; 124.511,-28.956 124.511,-23.804
  text "ALL ARTWORK VIEWED FROM TOP SIDE" at -5.804,-16.654 h1.52
  text "BOARD #:" at 57.099,-16.654 h1.52
  text ".PRJ_Number" at 70.955,-16.654 h1.52
  text "REV:" at 92.405,-16.654 h1.52
  text ".PCB_Rev" at 99.809,-16.654 h1.52
  text "SVN REV:" at 113.69,-16.654 h1.52
  text ".VersionControl_RevNumber" at 126.543,-16.654 h1.52
  text "LAYER NAME =" at -5.804,-21.806 h1.52
  text "TID #:" at 57.099,-21.819 h1.52
  text ".TID" at 70.955,-21.819 h1.52
  text "PLOT NAME =" at -5.804,-27.034 h1.52
  text ".plot_File_Name" at 14.656,-27.034 h1.52
  text "GENERATED    :" at 57.15,-27.034 h1.52
  text ".Print_Date" at 79.235,-27.034 h1.52
  text ".Print_Time" at 97.752,-27.034 h1.52
  text "TEXAS INSTRUMENTS" at 129.87,-27.034 h1.52
M12 Stackup:
  drawing of 191 lines, arcs and shapes, not listed
  text "Layer" at 248.675,198.882 h1.52
  text "Name" at 259.086,198.882 h1.52
  text "Material" at 282.702,198.882 h1.52
  text "Thickness" at 304.54,198.882 h1.52
  text "Constant" at 321.046,198.882 h1.52
  text "Board Layer Stack" at 335.52,198.882 h1.52
  text "1" at 248.675,195.834 h1.52
  text "Top Overlay" at 259.086,195.834 h1.52
  text "2" at 248.675,192.786 h1.52
  text "Top Solder" at 259.086,192.786 h1.52
  text "Solder Resist" at 282.702,192.786 h1.52
  text "0.40mil" at 304.54,192.786 h1.52
  text "3.5" at 321.046,192.786 h1.52
  text "3" at 248.675,189.738 h1.52
  text "Top Layer" at 259.086,189.738 h1.52
  text "Copper" at 282.702,189.738 h1.52
  text "1.40mil" at 304.54,189.738 h1.52
  text "4" at 248.675,186.69 h1.52
  text "Dielectric1" at 259.086,186.69 h1.52
  text "FR-4" at 282.702,186.69 h1.52
  text "59.20mil" at 304.54,186.69 h1.52
  text "4.8" at 321.046,186.69 h1.52
  text "5" at 248.675,183.642 h1.52
  text "Bottom Layer" at 259.086,183.642 h1.52
  text "Copper" at 282.702,183.642 h1.52
  text "1.40mil" at 304.54,183.642 h1.52
  text "6" at 248.675,180.594 h1.52
  text "Bottom Solder" at 259.086,180.594 h1.52
  text "Solder Resist" at 282.702,180.594 h1.52
  text "0.40mil" at 304.54,180.594 h1.52
  text "3.5" at 321.046,180.594 h1.52
  text "7" at 248.675,177.546 h1.52
  text "Bottom Overlay" at 259.086,177.546 h1.52
  text ".Layer_Name" at 14.656,-21.806 h1.52
M13 Component Bodies Top:
  text ".Layer_Name" at 14.656,-21.806 h1.52
M14 Component Bodies Bottom:
  text ".Layer_Name" at 14.656,-21.806 h1.52
M15 Courtyards Top:
  text ".Layer_Name" at 14.656,-21.806 h1.52
M16 Courtyards Bottom:
  text ".Layer_Name" at 14.656,-21.806 h1.52
Drill Drawing:
  text ".Layer_Name" at 14.656,-21.806 h1.52
M17 Embedded Cavity:
  text ".Layer_Name" at 14.656,-21.806 h1.52
M18 Embedded Assembly:
  text ".Layer_Name" at 14.656,-21.806 h1.52
M19 Embedded Keepout:
  text ".Layer_Name" at 14.656,-21.806 h1.52

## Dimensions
0,-10.16 to 25.4,-10.16 on M2 Board Dimensions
